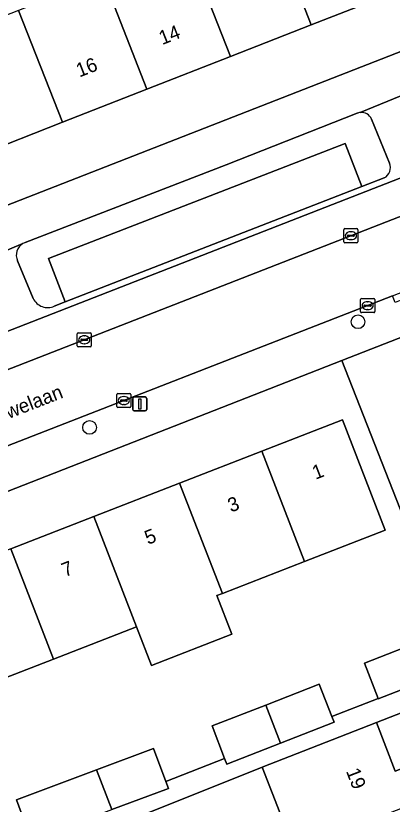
# Model space of a CAD drawing. Extents: x 159680 to 160786, y 387323 to 388340.
# Drawn here: x 160062.7 to 160089.5, y 387851.7 to 387907.8 of the extents above; entities that cross this region are included whole.
import ezdxf

# ---------------------------------------------------------------- set-up
doc = ezdxf.new("R2010")
doc.units = 0
for name, color, linetype in [('IMGEO_Boom', 7, 'Continuous'), ('IMGEO_Erf', 7, 'Continuous'), ('IMGEO_Groenvoorziening', 7, 'Continuous'), ('IMGEO_Kolk', 7, 'Continuous'), ('IMGEO_Lichtmast', 7, 'Continuous'), ('IMGEO_Openbare_ruimte_label', 7, 'Continuous'), ('IMGEO_Pand', 7, 'Continuous'), ('IMGEO_Pand_nummerreeks', 7, 'Continuous'), ('IMGEO_Parkeervlak_open', 7, 'Continuous'), ('IMGEO_Rijbaan_lokaal_open', 7, 'Continuous'), ('IMGEO_Voetpad_open', 7, 'Continuous')]:
    doc.layers.add(name, color=color, linetype=linetype)

msp = doc.modelspace()

# ---------------------------------------------------------------- linework, layer by layer
at = {"layer": 'IMGEO_Boom'}
for centre in [(160087.037, 387886.065), (160067.934, 387878.547)]:
    msp.add_circle(centre, 0.489, dxfattribs=at)
at = {"layer": 'IMGEO_Erf'}
msp.add_lwpolyline([(160114.506, 387914.836), (160113.014, 387918.655), (160107.176, 387916.369), (160101.289, 387914.065), (160095.458, 387911.782), (160089.446, 387909.428), (160083.711, 387907.182), (160077.958, 387904.93), (160072.016, 387902.604), (160065.996, 387900.247), (160059.969, 387897.887), (160061.446, 387894.107)], close=True, dxfattribs=at)
for points in [[(160063.739, 387849.344), (160062.722, 387852.054), (160068.423, 387854.192), (160072.479, 387855.713), (160073.356, 387853.373), (160077.546, 387855.006), (160076.648, 387857.311), (160080.474, 387858.801), (160084.279, 387860.283), (160085.174, 387857.985), (160088.474, 387859.271), (160087.498, 387861.772), (160091.99, 387863.525), (160093.454, 387864.097), (160090.286, 387872.143), (160085.896, 387883.295), (160035.948, 387863.765)], [(160062.317, 387869.913), (160068.235, 387872.211), (160074.344, 387874.583), (160080.185, 387876.852), (160085.931, 387879.083), (160088.976, 387871.243), (160083.23, 387869.012), (160077.389, 387866.743), (160076.989, 387866.588), (160078.059, 387863.832), (160072.35, 387861.616), (160071.28, 387864.371), (160065.362, 387862.073), (160059.518, 387859.803)], [(160092.553, 387859.189), (160088.342, 387857.548), (160089.686, 387854.104), (160091.242, 387854.711), (160092.194, 387852.273), (160093.145, 387849.835)], [(160082.517, 387848.488), (160080.218, 387854.378), (160070.559, 387850.515)]]:
    msp.add_lwpolyline(points, dxfattribs=at)
at = {"layer": 'IMGEO_Groenvoorziening'}
for points in [[(160086.967, 387900.885), (160077.657, 387897.22), (160063.341, 387891.695)], [(160089.276, 387897.337), (160088.001, 387900.469)], [(160065.002, 387890.548), (160086.115, 387898.748), (160087.309, 387895.671), (160088.9, 387896.289)], [(160062.81, 387890.4), (160063.925, 387887.721)], [(160065.422, 387887.17), (160066.196, 387887.471), (160065.002, 387890.548)]]:
    msp.add_lwpolyline(points, dxfattribs=at)
msp.add_lwpolyline([(160066.196, 387887.471), (160087.309, 387895.671), (160086.115, 387898.748), (160065.002, 387890.548)], close=True, dxfattribs=at)
for centre, radius, start, end in [((160087.29, 387900.091), 0.857, 96.1987, 112.1081), ((160087.272, 387900.151), 0.795, 23.5448, 95.4121), ((160088.52, 387897.017), 0.821, 297.5632, 22.963), ((160063.657, 387890.809), 0.941, 120.7634, 205.7604), ((160063.676, 387890.774), 0.98, 109.959, 120.6437), ((160064.948, 387888.192), 1.127, 204.7236, 294.8622)]:
    msp.add_arc(centre, radius, start, end, dxfattribs=at)
at = {"layer": 'IMGEO_Kolk'}
for p, q in [((160086.031, 387891.755), (160086.031, 387892.607)), ((160086.106, 387892.681), (160086.958, 387892.681)), ((160086.519, 387892.461), (160086.544, 387892.461)), ((160087.032, 387892.607), (160087.032, 387891.755)), ((160086.29, 387892.175), (160086.29, 387892.187)), ((160086.728, 387892.138), (160086.33, 387892.138)), ((160086.333, 387892.224), (160086.731, 387892.224)), ((160086.542, 387891.901), (160086.517, 387891.901)), ((160086.774, 387892.187), (160086.774, 387892.175)), ((160086.958, 387891.681), (160086.106, 387891.681)), ((160087.225, 387886.781), (160087.225, 387887.633)), ((160087.3, 387887.707), (160088.152, 387887.707)), ((160087.527, 387887.25), (160087.925, 387887.25)), ((160087.713, 387887.487), (160087.738, 387887.487)), ((160088.226, 387887.633), (160088.226, 387886.781)), ((160088.152, 387886.707), (160087.3, 387886.707)), ((160087.484, 387887.201), (160087.484, 387887.213)), ((160087.922, 387887.164), (160087.524, 387887.164)), ((160087.736, 387886.927), (160087.711, 387886.927)), ((160087.968, 387887.213), (160087.968, 387887.201)), ((160067.055, 387884.352), (160067.055, 387885.204)), ((160067.13, 387885.278), (160067.982, 387885.278)), ((160067.543, 387885.058), (160067.568, 387885.058)), ((160068.056, 387885.204), (160068.056, 387884.352)), ((160067.314, 387884.772), (160067.314, 387884.784)), ((160067.752, 387884.735), (160067.354, 387884.735)), ((160067.357, 387884.821), (160067.755, 387884.821)), ((160067.566, 387884.498), (160067.541, 387884.498)), ((160067.798, 387884.784), (160067.798, 387884.772)), ((160067.982, 387884.278), (160067.13, 387884.278)), ((160069.872, 387880.029), (160069.872, 387880.881)), ((160069.947, 387880.955), (160070.799, 387880.955)), ((160070.36, 387880.735), (160070.385, 387880.735)), ((160070.873, 387880.881), (160070.873, 387880.029)), ((160070.799, 387879.955), (160069.947, 387879.955)), ((160070.131, 387880.449), (160070.131, 387880.461)), ((160070.569, 387880.412), (160070.171, 387880.412)), ((160070.174, 387880.498), (160070.572, 387880.498)), ((160070.383, 387880.175), (160070.358, 387880.175)), ((160070.615, 387880.461), (160070.615, 387880.449))]:
    msp.add_line(p, q, dxfattribs=at)
for points in [[(160086.031, 387891.755), (160086.031, 387892.607)], [(160086.106, 387892.681), (160086.958, 387892.681)], [(160087.032, 387892.607), (160087.032, 387891.755)], [(160086.958, 387891.681), (160086.106, 387891.681)], [(160087.225, 387886.781), (160087.225, 387887.633)], [(160087.3, 387887.707), (160088.152, 387887.707)], [(160088.226, 387887.633), (160088.226, 387886.781)], [(160088.152, 387886.707), (160087.3, 387886.707)], [(160067.055, 387884.352), (160067.055, 387885.204)], [(160067.13, 387885.278), (160067.982, 387885.278)], [(160068.056, 387885.204), (160068.056, 387884.352)], [(160067.982, 387884.278), (160067.13, 387884.278)], [(160069.872, 387880.029), (160069.872, 387880.881)], [(160069.947, 387880.955), (160070.799, 387880.955)], [(160070.873, 387880.881), (160070.873, 387880.029)], [(160070.799, 387879.955), (160069.947, 387879.955)]]:
    msp.add_lwpolyline(points, dxfattribs=at)
for centre, radius, start, end in [((160086.108, 387892.605), 0.0765, 91.552, 178.448), ((160086.108, 387892.605), 0.0765, 91.552, 178.448), ((160086.956, 387892.605), 0.0765, 1.552, 88.448), ((160086.956, 387892.605), 0.0765, 1.552, 88.448), ((160086.108, 387891.757), 0.0765, 181.552, 268.448), ((160086.108, 387891.757), 0.0765, 181.552, 268.448), ((160086.33, 387892.184), 0.0403, 85.8775, 175.7526), ((160086.327, 387892.174), 0.0366, 178.938, 274.7102), ((160086.731, 387892.181), 0.043, 264.8664, 352.4533), ((160086.735, 387892.186), 0.0386, 1.7309, 96.639), ((160086.956, 387891.757), 0.0765, 271.552, 358.448), ((160086.956, 387891.757), 0.0765, 271.552, 358.448), ((160087.302, 387887.631), 0.0765, 91.552, 178.448), ((160087.302, 387887.631), 0.0765, 91.552, 178.448), ((160087.524, 387887.21), 0.0403, 85.8775, 175.7526), ((160087.929, 387887.212), 0.0386, 1.7309, 96.639), ((160088.15, 387887.631), 0.0765, 1.552, 88.448), ((160088.15, 387887.631), 0.0765, 1.552, 88.448), ((160087.302, 387886.783), 0.0765, 181.552, 268.448), ((160087.302, 387886.783), 0.0765, 181.552, 268.448), ((160087.521, 387887.2), 0.0366, 178.938, 274.7102), ((160087.925, 387887.207), 0.043, 264.8664, 352.4533), ((160088.15, 387886.783), 0.0765, 271.552, 358.448), ((160088.15, 387886.783), 0.0765, 271.552, 358.448), ((160067.132, 387885.202), 0.0765, 91.552, 178.448), ((160067.132, 387885.202), 0.0765, 91.552, 178.448), ((160067.98, 387885.202), 0.0765, 1.552, 88.448), ((160067.98, 387885.202), 0.0765, 1.552, 88.448), ((160067.354, 387884.781), 0.0403, 85.8775, 175.7526), ((160067.351, 387884.771), 0.0366, 178.938, 274.7102), ((160067.755, 387884.778), 0.043, 264.8664, 352.4533), ((160067.759, 387884.783), 0.0386, 1.7309, 96.639), ((160067.132, 387884.354), 0.0765, 181.552, 268.448), ((160067.132, 387884.354), 0.0765, 181.552, 268.448), ((160067.98, 387884.354), 0.0765, 271.552, 358.448), ((160067.98, 387884.354), 0.0765, 271.552, 358.448), ((160069.949, 387880.879), 0.0765, 91.552, 178.448), ((160069.949, 387880.879), 0.0765, 91.552, 178.448), ((160070.797, 387880.879), 0.0765, 1.552, 88.448), ((160070.797, 387880.879), 0.0765, 1.552, 88.448), ((160069.949, 387880.031), 0.0765, 181.552, 268.448), ((160069.949, 387880.031), 0.0765, 181.552, 268.448), ((160070.171, 387880.458), 0.0403, 85.8775, 175.7526), ((160070.168, 387880.448), 0.0366, 178.938, 274.7102), ((160070.572, 387880.455), 0.043, 264.8664, 352.4533), ((160070.576, 387880.46), 0.0386, 1.7309, 96.639), ((160070.797, 387880.031), 0.0765, 271.552, 358.448), ((160070.797, 387880.031), 0.0765, 271.552, 358.448)]:
    msp.add_arc(centre, radius, start, end, dxfattribs=at)
for centre, major_axis, ratio, start_param, end_param in [((160086.518, 387892.181), (-0.387, 0.002), 0.722429, 4.712389, 7.853982), ((160086.543, 387892.181), (-0.39, 0.002), 0.717154, 1.570796, 4.712389), ((160087.712, 387887.207), (-0.387, 0.002), 0.722429, 4.712389, 7.853982), ((160087.737, 387887.207), (-0.39, 0.002), 0.717154, 1.570796, 4.712389), ((160067.542, 387884.778), (-0.387, 0.002), 0.722429, 4.712389, 7.853982), ((160067.567, 387884.778), (-0.39, 0.002), 0.717154, 1.570796, 4.712389), ((160070.359, 387880.455), (-0.387, 0.002), 0.722429, 4.712389, 7.853982), ((160070.384, 387880.455), (-0.39, 0.002), 0.717154, 1.570796, 4.712389)]:
    msp.add_ellipse(centre, major_axis=major_axis, ratio=ratio, start_param=start_param, end_param=end_param, dxfattribs=at)
at = {"layer": 'IMGEO_Lichtmast'}
for p, q in [((160071.009, 387879.813), (160071.009, 387880.613)), ((160071.009, 387880.613), (160071.009, 387879.813)), ((160071.109, 387880.713), (160071.899, 387880.713)), ((160071.899, 387880.713), (160071.109, 387880.713)), ((160071.999, 387880.613), (160071.999, 387879.813)), ((160071.999, 387879.813), (160071.999, 387880.613)), ((160071.899, 387879.713), (160071.109, 387879.713)), ((160071.109, 387879.713), (160071.899, 387879.713))]:
    msp.add_line(p, q, dxfattribs=at)
msp.add_lwpolyline([(160071.429, 387880.588), (160071.579, 387880.588), (160071.579, 387879.838), (160071.429, 387879.838), (160071.429, 387880.588)], dxfattribs=at)
for centre, start, end in [((160071.109, 387880.613), 90, 180), ((160071.109, 387880.613), 90, 180), ((160071.899, 387880.613), 0, 90), ((160071.899, 387880.613), 360, 90), ((160071.109, 387879.813), 180, 270), ((160071.109, 387879.813), 180, 270), ((160071.899, 387879.813), 270, 0), ((160071.899, 387879.813), 270, 0)]:
    msp.add_arc(centre, 0.1, start, end, dxfattribs=at)
at = {"layer": 'IMGEO_Pand'}
for points in [[(160080.594, 387915.144), (160080.311, 387915.033), (160079.044, 387918.269), (160073.573, 387916.127), (160074.84, 387912.891), (160077.958, 387904.93), (160083.711, 387907.182)], [(160086.329, 387917.389), (160080.594, 387915.144), (160083.711, 387907.182), (160089.446, 387909.428)], [(160072.016, 387902.604), (160077.958, 387904.93), (160074.84, 387912.891), (160068.898, 387910.564)], [(160065.996, 387900.247), (160072.016, 387902.604), (160068.898, 387910.564), (160062.879, 387908.208)], [(160062.879, 387908.208), (160056.844, 387905.845), (160058.141, 387902.542), (160059.969, 387897.887), (160065.996, 387900.247)], [(160083.23, 387869.012), (160088.976, 387871.243), (160085.931, 387879.083), (160080.185, 387876.852)], [(160077.389, 387866.743), (160083.23, 387869.012), (160080.185, 387876.852), (160074.344, 387874.583)], [(160074.344, 387874.583), (160068.235, 387872.211), (160071.28, 387864.371), (160072.35, 387861.616), (160078.059, 387863.832), (160076.989, 387866.588), (160077.389, 387866.743)], [(160068.235, 387872.211), (160062.317, 387869.913), (160065.362, 387862.073), (160071.28, 387864.371)], [(160059.518, 387859.803), (160065.362, 387862.073), (160062.317, 387869.913), (160056.473, 387867.643)], [(160092.208, 387862.966), (160091.99, 387863.525), (160087.498, 387861.772), (160088.474, 387859.271), (160088.483, 387859.248), (160091.996, 387860.619), (160092.975, 387861.001)], [(160084.279, 387860.283), (160080.474, 387858.801), (160081.527, 387856.088), (160085.335, 387857.571), (160085.174, 387857.985)], [(160080.474, 387858.801), (160076.648, 387857.311), (160077.546, 387855.006), (160077.705, 387854.599), (160081.527, 387856.088)], [(160092.194, 387852.273), (160091.242, 387854.711), (160089.686, 387854.104), (160088.342, 387857.548), (160083.685, 387855.731), (160080.218, 387854.378), (160082.517, 387848.488)], [(160072.479, 387855.713), (160068.423, 387854.192), (160069.523, 387851.36), (160073.545, 387852.869), (160073.356, 387853.373)], [(160068.423, 387854.192), (160062.722, 387852.054), (160063.739, 387849.344), (160063.789, 387849.21), (160069.523, 387851.36)]]:
    msp.add_lwpolyline(points, close=True, dxfattribs=at)
at = {"layer": 'IMGEO_Parkeervlak_open'}
for points in [[(160114.064, 387905.61), (160104.557, 387901.943), (160056.569, 387883.223), (160005.588, 387863.282)], [(160003.091, 387859.574), (160004.237, 387860.02), (160057.495, 387880.852), (160105.478, 387899.569)], [(160091.41, 387885.467), (160085.896, 387883.295), (160090.286, 387872.143), (160090.843, 387872.365), (160093.94, 387873.601)]]:
    msp.add_lwpolyline(points, dxfattribs=at)
at = {"layer": 'IMGEO_Rijbaan_lokaal_open'}
msp.add_lwpolyline([(160136.795, 387911.888), (160118.168, 387904.562), (160105.478, 387899.569), (160057.495, 387880.852), (160004.237, 387860.02), (160003.091, 387859.574), (160000, 387858.37), (159981.294, 387851.087), (159982.917, 387846.434), (160000, 387853.068), (160013.528, 387858.321), (160018.212, 387860.145), (160023.216, 387862.094), (160029.506, 387864.544), (160059.275, 387876.138), (160089.502, 387887.898), (160095.351, 387890.173), (160102.067, 387892.786), (160116.683, 387898.471), (160118.964, 387899.358), (160138.256, 387907.046), (160138.953, 387907.297), (160142.807, 387908.712)], dxfattribs=at)
at = {"layer": 'IMGEO_Voetpad_open'}
for points in [[(160114.072, 387911.049), (160114.271, 387910.688), (160114.869, 387909.226), (160115.857, 387906.811), (160118.168, 387904.562), (160136.795, 387911.888), (160140.836, 387913.368), (160142.084, 387913.853), (160140.13, 387916.234), (160120.676, 387908.594), (160118.757, 387907.847), (160118.086, 387909.722), (160117.335, 387911.726), (160116.002, 387915.162), (160115.897, 387915.38), (160115.683, 387915.296), (160114.506, 387914.836), (160061.446, 387894.107), (160060.118, 387893.588), (160001.03, 387870.503), (160000, 387870.101), (159999.652, 387869.965), (160000, 387869.051), (160001.74, 387864.48)], [(160087.197, 387900.943), (160090.08, 387902.125), (160101.469, 387906.609)], [(160005.14, 387864.473), (160005.588, 387863.282), (160056.569, 387883.223), (160104.557, 387901.943), (160114.064, 387905.61)], [(160090.08, 387902.125), (160087.197, 387900.943)], [(160063.341, 387891.695), (160077.657, 387897.22), (160086.967, 387900.885)], [(160088.001, 387900.469), (160089.276, 387897.337)], [(160088.9, 387896.289), (160087.309, 387895.671), (160066.196, 387887.471), (160065.422, 387887.17)], [(160033.043, 387879.891), (160049.876, 387886.384), (160060.321, 387890.421), (160063.176, 387891.617)], [(160063.176, 387891.617), (160060.321, 387890.421)], [(160063.925, 387887.721), (160062.81, 387890.4)], [(160070.559, 387850.515), (160080.218, 387854.378), (160083.685, 387855.731), (160088.342, 387857.548), (160092.553, 387859.189), (160091.996, 387860.619), (160088.483, 387859.248), (160088.474, 387859.271), (160085.174, 387857.985), (160085.335, 387857.571), (160081.527, 387856.088), (160077.705, 387854.599), (160077.546, 387855.006), (160073.356, 387853.373), (160073.545, 387852.869), (160069.523, 387851.36)]]:
    msp.add_lwpolyline(points, dxfattribs=at)
msp.add_lwpolyline([(160085.896, 387883.295), (160091.41, 387885.467), (160090.509, 387887.754), (160089.681, 387887.432), (160089.502, 387887.898), (160059.275, 387876.138), (160029.506, 387864.544), (160029.686, 387864.078), (160024.281, 387861.973), (160025.23, 387859.629), (160030.234, 387861.596), (160034.966, 387863.392), (160040.087, 387850.124), (160041.055, 387850.499), (160040.271, 387852.536), (160035.948, 387863.765)], close=True, dxfattribs=at)
for centre, radius, start, end in [((160087.29, 387900.091), 0.857, 96.1987, 112.1081), ((160087.272, 387900.151), 0.795, 23.5448, 95.4121), ((160088.52, 387897.017), 0.821, 297.5632, 22.963), ((160063.657, 387890.809), 0.941, 120.7634, 205.7604), ((160063.676, 387890.774), 0.98, 109.959, 120.6437), ((160064.948, 387888.192), 1.127, 204.7236, 294.8622)]:
    msp.add_arc(centre, radius, start, end, dxfattribs=at)

# ---------------------------------------------------------------- texts
at = {"layer": 'IMGEO_Openbare_ruimte_label'}
msp.add_text('Betuwelaan', height=1, rotation=21.2802, dxfattribs=at).set_placement((160059.616, 387878.143))
at = {"layer": 'IMGEO_Pand_nummerreeks'}
for s, rotation, p in [('14', 21.3812, (160073.1, 387905.734)), ('16', 21.3812, (160067.207, 387903.427)), ('1', 21.2237, (160084.013, 387874.819)), ('3', 21.2237, (160077.996, 387872.483)), ('5', 21.2224, (160072.086, 387870.188)), ('7', 21.2237, (160066.176, 387867.892)), ('19', 291.351, (160086.17, 387854.097))]:
    msp.add_text(s, height=1, rotation=rotation, dxfattribs=at).set_placement(p)

doc.saveas('drawing.dxf')
